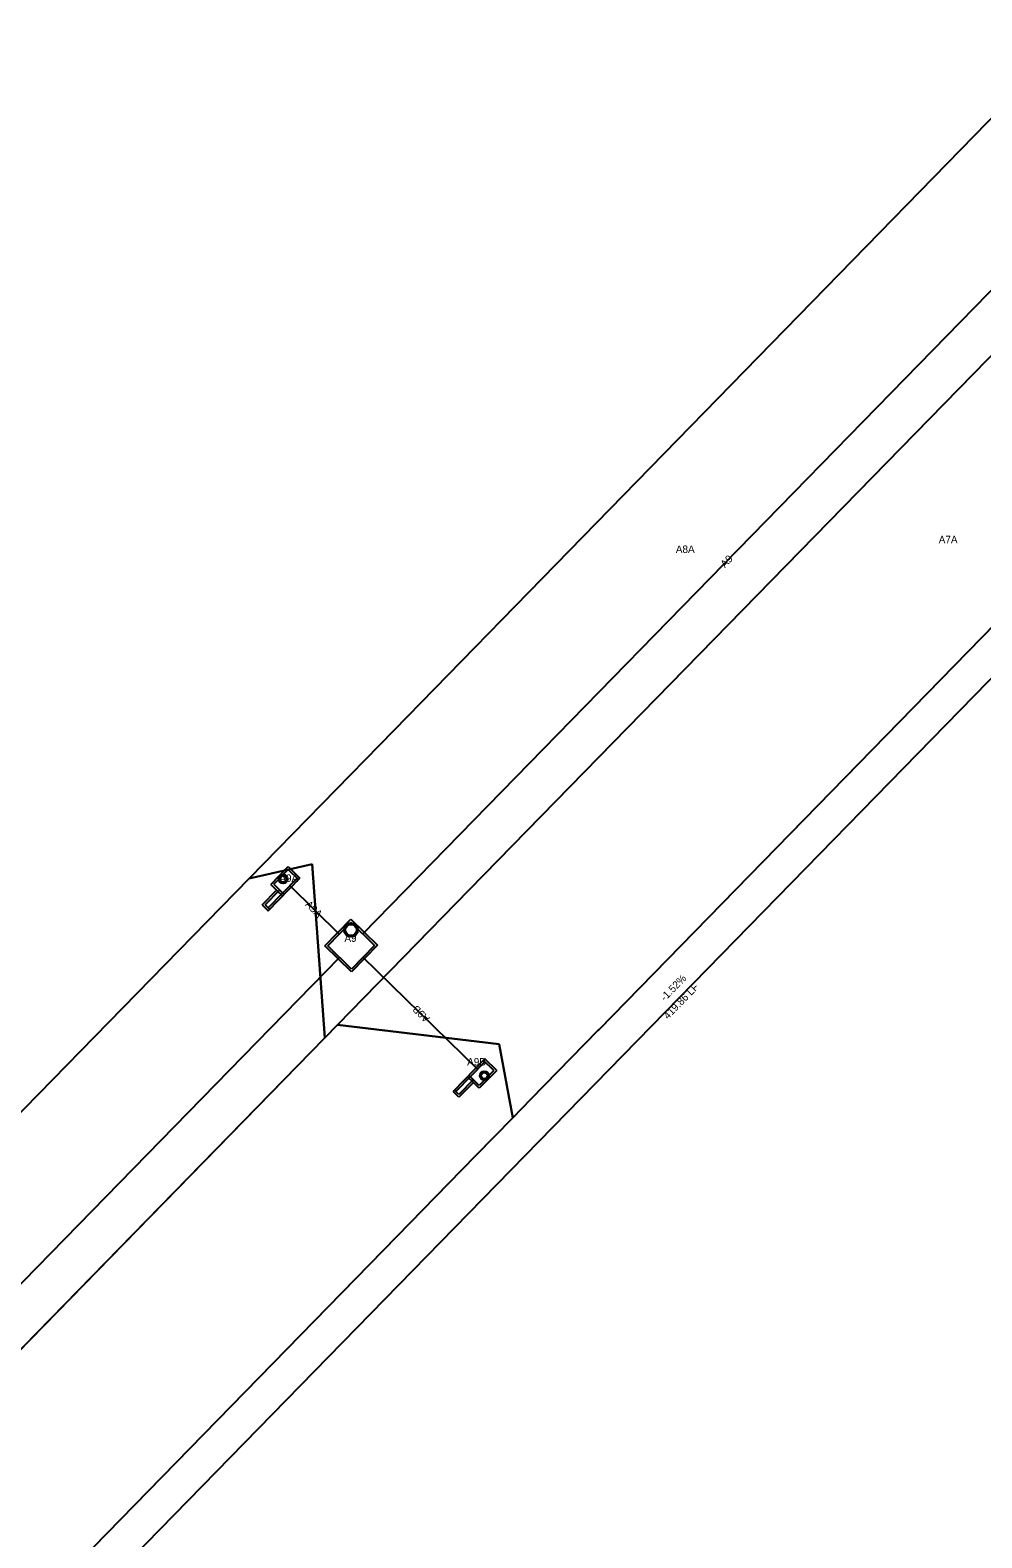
# Model space of a CAD drawing. Extents: x 2252703 to 2264864, y 13787568 to 13790989.
# Drawn here: x 2253731.9 to 2253962, y 13789520.9 to 13789885.2 of the extents above; entities that cross this region are included whole.
import ezdxf

# ---------------------------------------------------------------- set-up
doc = ezdxf.new("R2010")
doc.units = 0
for name, color, linetype in [('D_BOXES_1', 7, 'Continuous'), ('D_DRAIN_MISC', 7, 'Continuous'), ('D_DRAIN_NOTES_1', 7, 'Continuous'), ('D_DRN_AREA_X', 7, 'Continuous'), ('D_DRN_CHANNEL_FLOW', 7, 'Continuous'), ('D_INLET_1', 7, 'Continuous'), ('D_PIPES_1', 7, 'Continuous')]:
    doc.layers.add(name, color=color, linetype=linetype)

msp = doc.modelspace()

# ---------------------------------------------------------------- linework, layer by layer
at = {"layer": 'D_BOXES_1'}
for p, q in [((2253812.35, 13789666.84), (2253988.48, 13789847.07)), ((2253567.72, 13789416.52), (2253806.76, 13789661.12))]:
    msp.add_line(p, q, dxfattribs=at)
at = {"layer": 'D_DRAIN_MISC'}
for p, q in [((2253792.57, 13789680.58), (2253792.57, 13789680.58)), ((2253795.39, 13789681.32), (2253795.39, 13789681.32)), ((2253791.89, 13789677.74), (2253791.89, 13789677.74)), ((2253793.64, 13789679.53), (2253793.64, 13789679.53)), ((2253794.71, 13789678.48), (2253794.71, 13789678.48)), ((2253806.69, 13789666.77), (2253806.69, 13789666.77)), ((2253812.35, 13789666.84), (2253812.35, 13789666.84)), ((2253809.55, 13789663.98), (2253809.55, 13789663.98)), ((2253806.76, 13789661.12), (2253806.76, 13789661.12)), ((2253812.41, 13789661.18), (2253812.41, 13789661.18)), ((2253840.13, 13789634.1), (2253840.13, 13789634.1)), ((2253842.95, 13789634.84), (2253842.95, 13789634.84)), ((2253839.45, 13789631.26), (2253839.45, 13789631.26)), ((2253841.2, 13789633.05), (2253841.2, 13789633.05)), ((2253842.27, 13789632), (2253842.27, 13789632))]:
    msp.add_line(p, q, dxfattribs=at)
at = {"layer": 'D_DRN_AREA_X'}
for p, q in [((2254041.1, 13789885.17), (2253838.11, 13789677.46)), ((2253966.65, 13789866.22), (2253819.83, 13789715.98)), ((2253838.11, 13789677.46), (2253984.84, 13789827.6)), ((2253819.83, 13789715.98), (2253784.88, 13789680.23)), ((2253784.88, 13789680.23), (2253800.13, 13789683.67)), ((2253800.13, 13789683.67), (2253784.88, 13789680.23)), ((2253800.13, 13789683.67), (2253803.16, 13789641.7)), ((2253803.16, 13789641.7), (2253800.13, 13789683.67)), ((2253784.88, 13789680.23), (2253635.15, 13789527.01)), ((2253803.16, 13789641.7), (2253838.11, 13789677.46)), ((2253838.11, 13789677.46), (2253806.21, 13789644.82)), ((2253806.21, 13789644.82), (2253845.35, 13789640.18)), ((2253845.35, 13789640.18), (2253806.21, 13789644.82)), ((2253715.8, 13789552.3), (2253803.16, 13789641.7)), ((2253852.97, 13789626.85), (2253869.29, 13789643.54)), ((2253869.29, 13789643.54), (2253852.97, 13789626.85)), ((2253869.29, 13789643.54), (2253869.28, 13789643.54)), ((2253869.28, 13789643.54), (2253869.29, 13789643.54)), ((2253845.35, 13789640.18), (2253848.6, 13789622.38)), ((2253848.6, 13789622.38), (2253845.35, 13789640.18)), ((2253848.6, 13789622.38), (2253852.97, 13789626.85)), ((2253852.97, 13789626.85), (2253848.6, 13789622.38)), ((2253848.6, 13789622.38), (2253839.66, 13789613.23)), ((2253839.66, 13789613.23), (2253848.6, 13789622.38))]:
    msp.add_line(p, q, dxfattribs=at)
for points in [[(2254054.56, 13789833.13), (2253869.39, 13789643.66), (2253869.28, 13789643.54), (2253869.28, 13789643.54)], [(2253869.29, 13789643.54), (2253869.39, 13789643.65), (2254054.56, 13789833.13)], [(2253806.21, 13789644.82), (2253715.8, 13789552.3), (2253583.73, 13789417.16)], [(2253869.28, 13789643.54), (2253869.29, 13789643.54)], [(2253839.66, 13789613.23), (2253833.09, 13789606.51), (2253820.67, 13789593.8), (2253690.3, 13789460.4), (2253689.38, 13789459.45), (2253684.7, 13789454.66), (2253655.27, 13789424.55), (2253614.91, 13789383.25), (2253603.9, 13789371.99)], [(2253603.9, 13789371.99), (2253614.91, 13789383.25), (2253655.27, 13789424.55), (2253684.7, 13789454.66), (2253689.38, 13789459.45), (2253690.3, 13789460.4), (2253820.67, 13789593.8), (2253833.09, 13789606.51), (2253839.66, 13789613.23)]]:
    msp.add_lwpolyline(points, dxfattribs=at)
at = {"layer": 'D_DRN_CHANNEL_FLOW'}
msp.add_line((2253743.62, 13789502.8), (2254037.07, 13789803.07), dxfattribs=at)
msp.add_line((2253743.62, 13789502.8), (2254037.07, 13789803.07), dxfattribs=at)
at = {"layer": 'D_INLET_1'}
for p, q in [((2253790.11, 13789678.78), (2253794.31, 13789683.07)), ((2253790.82, 13789678.79), (2253794.32, 13789682.37)), ((2253794.31, 13789683.07), (2253797.17, 13789680.28)), ((2253794.32, 13789682.37), (2253796.82, 13789679.92)), ((2253788.05, 13789673.81), (2253791.54, 13789677.38)), ((2253788.76, 13789673.82), (2253792.25, 13789677.39)), ((2253789.47, 13789673.12), (2253796.46, 13789680.27)), ((2253789.48, 13789672.41), (2253797.17, 13789680.28)), ((2253790.11, 13789678.78), (2253791.54, 13789677.38)), ((2253790.82, 13789678.79), (2253793.32, 13789676.34)), ((2253791.54, 13789677.38), (2253792.97, 13789675.99)), ((2253788.05, 13789673.81), (2253789.48, 13789672.41)), ((2253788.76, 13789673.82), (2253789.83, 13789672.77)), ((2253803.19, 13789663.9), (2253809.48, 13789670.34)), ((2253803.9, 13789663.91), (2253809.49, 13789669.63)), ((2253809.48, 13789670.34), (2253815.92, 13789664.05)), ((2253809.49, 13789669.63), (2253815.21, 13789664.04)), ((2253809.63, 13789657.61), (2253803.19, 13789663.9)), ((2253809.62, 13789658.32), (2253803.9, 13789663.91)), ((2253815.21, 13789664.04), (2253809.62, 13789658.32)), ((2253815.92, 13789664.05), (2253809.63, 13789657.61)), ((2253841.87, 13789636.59), (2253834.18, 13789628.73)), ((2253841.88, 13789635.89), (2253834.89, 13789628.73)), ((2253844.73, 13789633.8), (2253840.53, 13789629.51)), ((2253844.02, 13789633.79), (2253840.53, 13789630.21)), ((2253844.02, 13789633.79), (2253841.52, 13789636.24)), ((2253844.73, 13789633.8), (2253841.87, 13789636.59)), ((2253839.1, 13789631.61), (2253835.6, 13789628.04)), ((2253839.1, 13789630.9), (2253835.61, 13789627.33)), ((2253839.1, 13789630.9), (2253837.67, 13789632.3)), ((2253840.53, 13789630.21), (2253838.02, 13789632.66)), ((2253840.53, 13789629.51), (2253839.1, 13789630.9)), ((2253835.61, 13789627.33), (2253834.18, 13789628.73)), ((2253835.6, 13789628.04), (2253834.53, 13789629.08))]:
    msp.add_line(p, q, dxfattribs=at)
for centre, radius in [((2253793.1, 13789680.05), 1.08), ((2253793.1, 13789680.05), 0.75), ((2253809.51, 13789667.75), 1.67), ((2253809.51, 13789667.75), 1.33), ((2253841.74, 13789632.53), 1.08), ((2253841.74, 13789632.53), 0.75)]:
    msp.add_circle(centre, radius, dxfattribs=at)
at = {"layer": 'D_PIPES_1'}
for p, q in [((2253794.71, 13789678.48), (2253806.69, 13789666.77)), ((2253840.13, 13789634.1), (2253812.41, 13789661.18))]:
    msp.add_line(p, q, dxfattribs=at)

# ---------------------------------------------------------------- texts
at = {"layer": 'D_DRAIN_NOTES_1'}
for s, p in [('A8A', (2253888.04, 13789758.85)), ('A7A', (2253951.6, 13789761.19)), ('A9A', (2253792.19, 13789679.38)), ('A9', (2253807.92, 13789664.88)), ('A9B', (2253837.59, 13789635))]:
    msp.add_text(s, height=1.8, dxfattribs=at).set_placement(p)
for s, rotation, p in [('A9', 45.6588, (2253899.92, 13789755.16)), ('A9A', 315.6588, (2253798.27, 13789673.75)), ('A9B', 135.6588, (2253828.71, 13789646.51))]:
    msp.add_text(s, height=1.8, rotation=rotation, dxfattribs=at).set_placement(p)
at = {"layer": 'D_DRN_CHANNEL_FLOW'}
for s, p in [('-1.52%', (2253885.41, 13789650.46)), ('419.86 LF', (2253886.13, 13789646.05))]:
    msp.add_text(s, height=1.8, rotation=45.6588, dxfattribs=at).set_placement(p)

doc.saveas('drawing.dxf')
